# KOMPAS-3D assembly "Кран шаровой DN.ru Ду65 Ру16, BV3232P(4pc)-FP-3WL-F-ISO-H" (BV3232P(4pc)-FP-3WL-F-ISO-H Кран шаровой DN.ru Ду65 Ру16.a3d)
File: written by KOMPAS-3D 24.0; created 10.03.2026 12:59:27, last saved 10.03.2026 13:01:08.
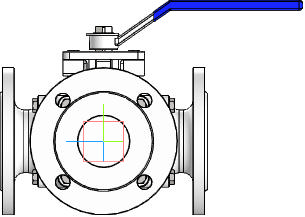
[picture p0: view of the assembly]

Document properties: Автор: R2D2; Полное имя файла: E:\Работа\Зайцев\BV3232P(4pc)-FP-3WL-F-ISO-H Кран шаровой DN.ru Ду15-100 Ру16\DN65\исходные материалы\BV3232P(4pc)-FP-3WL-F-ISO-H Кран шаровой DN.ru Ду65 Ру16.a3d

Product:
- Component [assembly]: Сборка1  | qty 1  | Масса: 31.822023; Автор: R2D2; source file: dn65_3d_step.a3d
- Part/product: Кран шаровой DN.ru Ду65 Ру16  | designation BV3232P(4pc)-FP-3WL-F-ISO-H
    Масса: 26.5
    Раздел спецификации: Прочие изделия
    Примечание: D160-36361

Referenced files in E:\Работа\Зайцев\BV3232P(4pc)-FP-3WL-F-ISO-H Кран шаровой DN.ru Ду15-100 Ру16\DN65\исходные материалы\: dn65_3d_step.a3d
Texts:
  BV3232P(4pc)-FP-3WL-F-ISO-H
  Сборка1 Сборка1
  Ось Z.Начало координат
  Ось Y.Начало координат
